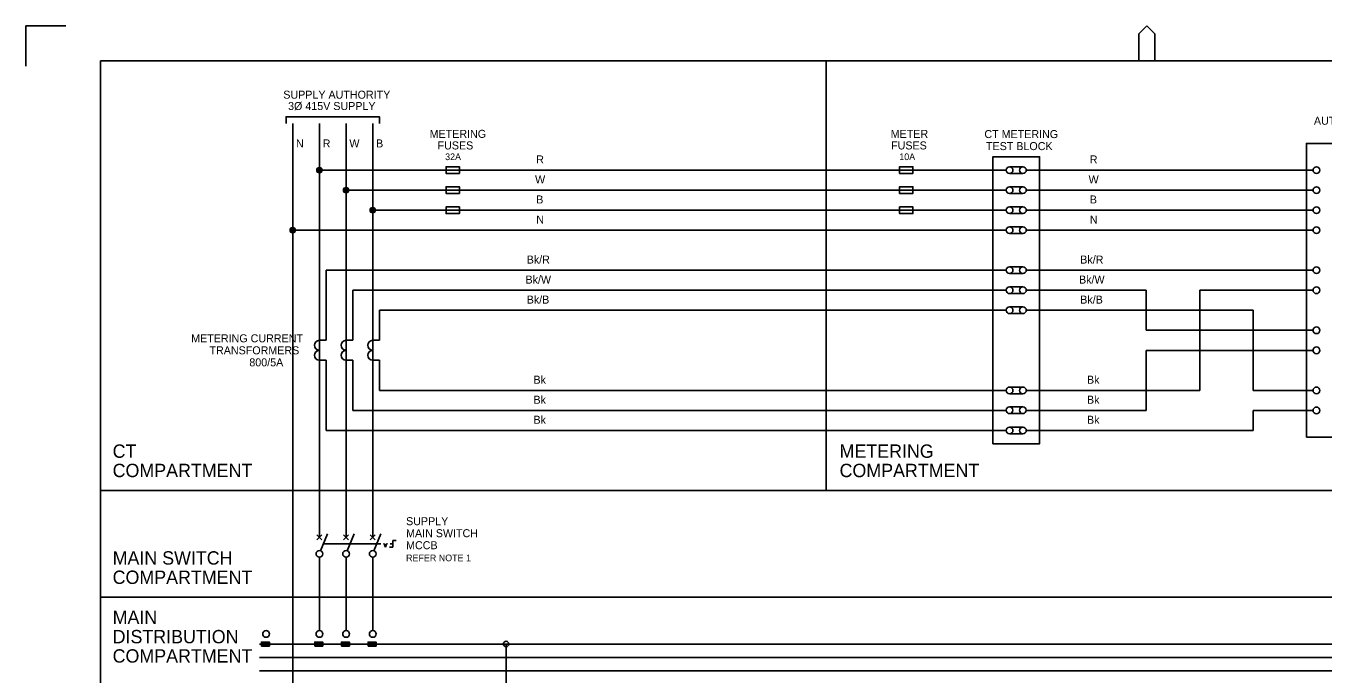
# Model space of a CAD drawing. Extents: x 0 to 841, y 0 to 594.
# Drawn here: x 0 to 486.2, y 351.2 to 594 of the extents above; entities that cross this region are included whole.
import ezdxf

# ---------------------------------------------------------------- set-up
doc = ezdxf.new("R2010")
doc.units = 0
for name, color, linetype in [('A1BORDER', 7, 'Continuous'), ('Level 1', 7, 'Continuous'), ('Level 10', 7, 'Continuous')]:
    doc.layers.add(name, color=color, linetype=linetype)

msp = doc.modelspace()

# ---------------------------------------------------------------- linework, layer by layer
at = {"layer": 'A1BORDER'}
for p, q in [((0, 594), (15, 594)), ((0, 579), (0, 594)), ((417.19, 591), (420.19, 594)), ((423.19, 591), (420.19, 594)), ((417.19, 581), (417.19, 591)), ((423.19, 581), (423.19, 591)), ((28, 581), (829, 581)), ((28, 581), (28, 15))]:
    msp.add_line(p, q, dxfattribs=at)
at = {"layer": 'Level 1'}
for p, q in [((300, 420), (300, 581)), ((100, 110), (100, 557.5)), ((110, 557.5), (110, 405)), ((120, 557.5), (120, 405)), ((130, 557.5), (130, 405)), ((110, 540), (367.5, 540)), ((368.75, 541.25), (373.75, 541.25)), ((375, 540), (482.5, 540)), ((483.75, 541.25), (483.75, 541.25)), ((368.75, 538.75), (373.75, 538.75)), ((483.75, 538.75), (483.75, 538.75)), ((120, 532.5), (367.5, 532.5)), ((368.75, 533.75), (373.75, 533.75)), ((368.75, 531.25), (373.75, 531.25)), ((375, 532.5), (482.5, 532.5)), ((483.75, 533.75), (483.75, 533.75)), ((483.75, 531.25), (483.75, 531.25)), ((368.75, 526.25), (373.75, 526.25)), ((483.75, 526.25), (483.75, 526.25)), ((130, 525), (367.5, 525)), ((368.75, 523.75), (373.75, 523.75)), ((375, 525), (482.5, 525)), ((483.75, 523.75), (483.75, 523.75)), ((100, 517.5), (367.5, 517.5)), ((368.75, 518.75), (373.75, 518.75)), ((368.75, 516.25), (373.75, 516.25)), ((375, 517.5), (482.5, 517.5)), ((483.75, 518.75), (483.75, 518.75)), ((483.75, 516.25), (483.75, 516.25)), ((112.5, 476.26), (112.5, 502.5)), ((112.5, 502.5), (367.5, 502.5)), ((368.75, 503.75), (373.75, 503.75)), ((368.75, 501.25), (373.75, 501.25)), ((375, 502.5), (482.5, 502.5)), ((483.75, 503.75), (483.75, 503.75)), ((483.75, 501.25), (483.75, 501.25)), ((368.75, 496.25), (373.75, 496.25)), ((483.75, 496.25), (483.75, 496.25)), ((122.5, 476.26), (122.5, 495)), ((122.5, 495), (367.5, 495)), ((368.75, 493.75), (373.75, 493.75)), ((375, 495), (420, 495)), ((420, 495), (420, 480)), ((440, 495), (482.5, 495)), ((440, 495), (440, 457.5)), ((483.75, 493.75), (483.75, 493.75)), ((132.5, 476.26), (132.5, 487.5)), ((132.5, 487.5), (367.5, 487.5)), ((368.75, 488.75), (373.75, 488.75)), ((368.75, 486.25), (373.75, 486.25)), ((375, 487.5), (460, 487.5)), ((460, 487.5), (460, 457.5)), ((420, 480), (482.5, 480)), ((483.75, 481.25), (483.75, 481.25)), ((483.75, 478.75), (483.75, 478.75)), ((420, 472.5), (482.5, 472.5)), ((420, 472.5), (420, 450)), ((483.75, 473.75), (483.75, 473.75)), ((112.5, 468.76), (112.5, 442.5)), ((122.5, 468.76), (122.5, 450)), ((132.5, 468.76), (132.5, 457.5)), ((483.75, 471.25), (483.75, 471.25)), ((132.5, 457.5), (367.5, 457.5)), ((368.75, 458.75), (373.75, 458.75)), ((375, 457.5), (440, 457.5)), ((460, 457.5), (482.5, 457.5)), ((483.75, 458.75), (483.75, 458.75)), ((368.75, 456.25), (373.75, 456.25)), ((483.75, 456.25), (483.75, 456.25)), ((122.5, 450), (367.5, 450)), ((368.73, 451.29), (373.73, 451.29)), ((368.73, 448.79), (373.73, 448.79)), ((375, 450), (420, 450)), ((460, 450), (482.5, 450)), ((460, 450), (460, 442.5)), ((483.75, 451.25), (483.75, 451.25)), ((483.75, 448.75), (483.75, 448.75)), ((112.5, 442.5), (367.5, 442.5)), ((368.75, 443.75), (373.75, 443.75)), ((375, 442.5), (460, 442.5)), ((368.75, 441.25), (373.75, 441.25)), ((28, 420), (829, 420)), ((110, 402.5), (110, 405)), ((110.46, 397.41), (113, 403.75)), ((120, 402.5), (120, 405)), ((120.46, 397.41), (123, 403.75)), ((130, 402.5), (130, 405)), ((130.46, 397.41), (133, 403.75)), ((109.06, 403.44), (110.94, 401.56)), ((110.94, 403.44), (109.06, 401.56)), ((111.5, 400), (131.5, 400)), ((119.06, 403.44), (120.94, 401.56)), ((120.94, 403.44), (119.06, 401.56)), ((129.06, 403.44), (130.94, 401.56)), ((130.94, 403.44), (129.06, 401.56)), ((110, 395), (110, 367.5)), ((120, 395), (120, 367.5)), ((130, 395), (130, 367.5)), ((28, 380), (829, 380)), ((87.5, 362.5), (685, 362.5)), ((88.25, 362.98), (91.25, 362.98)), ((88.25, 362.68), (91.25, 362.68)), ((88.25, 362.38), (91.25, 362.38)), ((88.25, 362.08), (91.25, 362.08)), ((88.25, 361.78), (91.25, 361.78)), ((108.25, 362.98), (111.25, 362.98)), ((108.25, 362.68), (111.25, 362.68)), ((108.25, 362.38), (111.25, 362.38)), ((108.25, 362.08), (111.25, 362.08)), ((108.25, 361.78), (111.25, 361.78)), ((118.25, 362.98), (121.25, 362.98)), ((118.25, 362.68), (121.25, 362.68)), ((118.25, 362.38), (121.25, 362.38)), ((118.25, 362.08), (121.25, 362.08)), ((118.25, 361.78), (121.25, 361.78)), ((128.25, 362.98), (131.25, 362.98)), ((128.25, 362.68), (131.25, 362.68)), ((128.25, 362.38), (131.25, 362.38)), ((128.25, 362.08), (131.25, 362.08)), ((128.25, 361.78), (131.25, 361.78)), ((180, 338.5), (180, 362.5)), ((87.5, 357.5), (685, 357.5)), ((87.5, 352.5), (685, 352.5))]:
    msp.add_line(p, q, dxfattribs=at)
msp.add_lwpolyline([(97.5, 557.5), (97.5, 560), (132.5, 560), (132.5, 557.5)], dxfattribs=at)
for points in [[(480, 440), (520, 440), (520, 550), (480, 550)], [(362.5, 437.5), (362.5, 545), (380, 545), (380, 437.5)], [(88.25, 361.75), (91.25, 361.75), (91.25, 363.25), (88.25, 363.25)], [(108.25, 361.75), (111.25, 361.75), (111.25, 363.25), (108.25, 363.25)], [(118.25, 361.75), (121.25, 361.75), (121.25, 363.25), (118.25, 363.25)], [(128.25, 361.75), (131.25, 361.75), (131.25, 363.25), (128.25, 363.25)]]:
    msp.add_lwpolyline(points, close=True, dxfattribs=at)
for centre, radius in [((368.75, 540), 1.25), ((373.75, 540), 1.25), ((368.75, 532.5), 1.25), ((373.75, 532.5), 1.25), ((368.75, 525), 1.25), ((373.75, 525), 1.25), ((368.75, 517.5), 1.25), ((373.75, 517.5), 1.25), ((368.75, 502.5), 1.25), ((373.75, 502.5), 1.25), ((368.75, 495), 1.25), ((373.75, 495), 1.25), ((368.75, 487.5), 1.25), ((373.75, 487.5), 1.25), ((368.75, 457.5), 1.25), ((373.75, 457.5), 1.25), ((368.73, 450.04), 1.25), ((373.73, 450.04), 1.25), ((368.75, 442.5), 1.25), ((373.75, 442.5), 1.25), ((110, 396.25), 1.25), ((120, 396.25), 1.25), ((130, 396.25), 1.25), ((90, 366.25), 1.25), ((110, 366.25), 1.25), ((120, 366.25), 1.25), ((130, 366.25), 1.25), ((180, 362.5), 1)]:
    msp.add_circle(centre, radius, dxfattribs=at)
at = {"layer": 'Level 10'}
for p, q in [((109, 540), (110.99, 540)), ((109.05, 540.3), (110.95, 540.3)), ((109.2, 540.6), (110.8, 540.6)), ((109.56, 540.9), (110.44, 540.9)), ((110, 541), (110, 541)), ((109.05, 539.7), (110.95, 539.7)), ((109.2, 539.4), (110.8, 539.4)), ((109.56, 539.1), (110.44, 539.1)), ((119, 532.5), (120.99, 532.5)), ((119.05, 532.8), (120.95, 532.8)), ((119.05, 532.2), (120.95, 532.2)), ((119.2, 533.1), (120.8, 533.1)), ((119.2, 531.9), (120.8, 531.9)), ((119.56, 533.4), (120.44, 533.4)), ((119.56, 531.6), (120.44, 531.6)), ((120, 533.5), (120, 533.5)), ((129.05, 525.3), (130.95, 525.3)), ((129.2, 525.6), (130.8, 525.6)), ((129.56, 525.9), (130.44, 525.9)), ((130, 526), (130, 526)), ((129, 525), (130.99, 525)), ((129.05, 524.7), (130.95, 524.7)), ((129.2, 524.4), (130.8, 524.4)), ((129.56, 524.1), (130.44, 524.1)), ((99, 517.5), (100.99, 517.5)), ((99.05, 517.8), (100.95, 517.8)), ((99.05, 517.2), (100.95, 517.2)), ((99.2, 518.1), (100.8, 518.1)), ((99.2, 516.9), (100.8, 516.9)), ((99.56, 518.4), (100.44, 518.4)), ((99.56, 516.6), (100.44, 516.6)), ((100, 518.5), (100, 518.5)), ((110, 476.26), (112.5, 476.26)), ((120, 476.26), (122.5, 476.26)), ((130, 476.26), (132.5, 476.26)), ((110, 468.76), (112.5, 468.76)), ((120, 468.76), (122.5, 468.76)), ((130, 468.76), (132.5, 468.76)), ((131.5, 400), (133, 400)), ((134, 400), (134.33, 400)), ((134.75, 398.75), (134.33, 400)), ((134.75, 398.75), (135.17, 400)), ((135.5, 400), (135.17, 400)), ((136.25, 398.75), (137.5, 398.75)), ((136.5, 400), (137.5, 400)), ((137.5, 398.75), (137.5, 401.25)), ((137.5, 401.25), (138.75, 401.25))]:
    msp.add_line(p, q, dxfattribs=at)
for points in [[(162.5, 540), (162.5, 541.25), (157.5, 541.25), (157.5, 538.75), (162.5, 538.75), (162.5, 540)], [(332.5, 540), (332.5, 541.25), (327.5, 541.25), (327.5, 538.75), (332.5, 538.75), (332.5, 540)], [(162.5, 532.5), (162.5, 533.75), (157.5, 533.75), (157.5, 531.25), (162.5, 531.25), (162.5, 532.5)], [(332.5, 532.5), (332.5, 533.75), (327.5, 533.75), (327.5, 531.25), (332.5, 531.25), (332.5, 532.5)], [(162.5, 525), (162.5, 526.25), (157.5, 526.25), (157.5, 523.75), (162.5, 523.75), (162.5, 525)], [(332.5, 525), (332.5, 526.25), (327.5, 526.25), (327.5, 523.75), (332.5, 523.75), (332.5, 525)]]:
    msp.add_lwpolyline(points, dxfattribs=at)
for centre, radius in [((110, 540), 1), ((483.75, 540), 1.25), ((120, 532.5), 1), ((483.75, 532.5), 1.25), ((130, 525), 1), ((483.75, 525), 1.25), ((100, 517.5), 1), ((483.75, 517.5), 1.25), ((483.75, 502.5), 1.25), ((483.75, 495), 1.25), ((483.75, 480), 1.25), ((483.75, 472.5), 1.25), ((483.75, 457.5), 1.25), ((483.75, 450), 1.25)]:
    msp.add_circle(centre, radius, dxfattribs=at)
for centre in [(110, 474.38), (110, 470.63), (120, 474.38), (120, 470.63), (130, 474.38), (130, 470.63)]:
    msp.add_arc(centre, 1.87, 90, 270, dxfattribs=at)

# ---------------------------------------------------------------- texts
at = {"layer": 'Level 1'}
for s, height, p in [('SUPPLY AUTHORITY', 3, (96.47, 566.76)), ('3Ø 415V SUPPLY', 3, (98.27, 562.51)), ('AUTHORITY METER', 3, (482.82, 557)), ('METERING', 3, (151.33, 552.09)), ('METER', 3, (324.17, 552.09)), ('CT METERING', 3, (359.3, 552)), ('N', 3, (101.25, 548.5)), ('R', 3, (111.25, 548.5)), ('W', 3, (121.25, 548.5)), ('B', 3, (131.25, 548.5)), ('FUSES', 3, (154.32, 547.75)), ('FUSES', 3, (324.32, 547.75)), ('TEST BLOCK', 3, (359.89, 547.5)), ('32A', 2.5, (157.14, 543.75)), ('R', 3, (191.3, 542.5)), ('10A', 2.5, (327.39, 543.75)), ('R', 3, (398.8, 542.5)), ('W', 3, (190.86, 535)), ('W', 3, (398.36, 535)), ('B', 3, (191.3, 527.5)), ('B', 3, (398.8, 527.5)), ('N', 3, (191.3, 520)), ('N', 3, (398.8, 520)), ('Bk/R', 3, (187.72, 505)), ('Bk/R', 3, (395.22, 505)), ('Bk/W', 3, (187.27, 497.5)), ('Bk/W', 3, (394.77, 497.5)), ('Bk/B', 3, (187.72, 490)), ('Bk/B', 3, (395.22, 490)), ('METERING CURRENT', 3, (61.94, 475.5)), ('TRANSFORMERS', 3, (68.81, 471)), ('800/5A', 3, (83.75, 466.5)), ('Bk', 3, (190.26, 460)), ('Bk', 3, (397.76, 460)), ('Bk', 3, (190.26, 452.5)), ('Bk', 3, (397.76, 452.5)), ('Bk', 3, (190.26, 445)), ('Bk', 3, (397.76, 445)), ('CT', 5, (32.5, 432.24)), ('METERING', 5, (305, 432.24)), ('COMPARTMENT', 5, (32.5, 425)), ('COMPARTMENT', 5, (305, 425)), ('SUPPLY', 3, (142.5, 407)), ('MAIN SWITCH', 3, (142.5, 402.5)), ('MCCB', 3, (142.5, 398)), ('MAIN SWITCH', 5, (32.5, 392.24)), ('REFER NOTE 1', 2.5, (142.5, 393.5)), ('COMPARTMENT', 5, (32.5, 385)), ('MAIN', 5, (32.5, 370)), ('DISTRIBUTION', 5, (32.5, 362.76)), ('COMPARTMENT', 5, (32.5, 355.53))]:
    msp.add_text(s, height=height, dxfattribs=at).set_placement(p)

doc.saveas('drawing.dxf')
